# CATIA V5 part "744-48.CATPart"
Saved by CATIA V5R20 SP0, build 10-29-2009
Part number: 744-48
Revision: TUTTO
Definition: NON CONOSCIUTO
Nomenclature: 744-48
Source: Unknown
Bounding box of the stored display mesh (mm): x -40 to 40, y -40.5 to 40, z -47 to 50
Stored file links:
  C:\Users\Utente\Desktop\IO LAVORO\3D X SITO CF\X SITO\744\744-48.CATPart
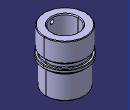
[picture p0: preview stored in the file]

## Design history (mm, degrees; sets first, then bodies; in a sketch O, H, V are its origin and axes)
Body1 "744-48 sol1" (main body)
  Solid1: solid without history
Body2 "IDV1M8_Ingrassatore-1"
  Solid2: solid without history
